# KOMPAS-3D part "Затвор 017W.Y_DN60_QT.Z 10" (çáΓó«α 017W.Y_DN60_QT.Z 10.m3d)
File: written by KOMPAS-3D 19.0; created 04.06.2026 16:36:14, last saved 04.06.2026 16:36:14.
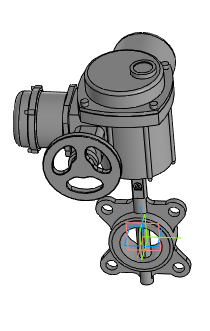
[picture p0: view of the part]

Document properties: Автор: Энергия; Полное имя файла: ..\..\..\3d для проектировщиков\017W разные\x.x Тип 017W.Y(S) Затвор дисковый поворотный межфланцевый\Затвор 017W.Y(S)_DN32-DN450_QT.Z\Затвор 017W.Y_DN60_QT.Z 10.a3d

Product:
- Part/product: Затвор 017W.Y_DN60_QT.Z 10
    Масса: 30.6284

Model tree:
1. Операция без истории:1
